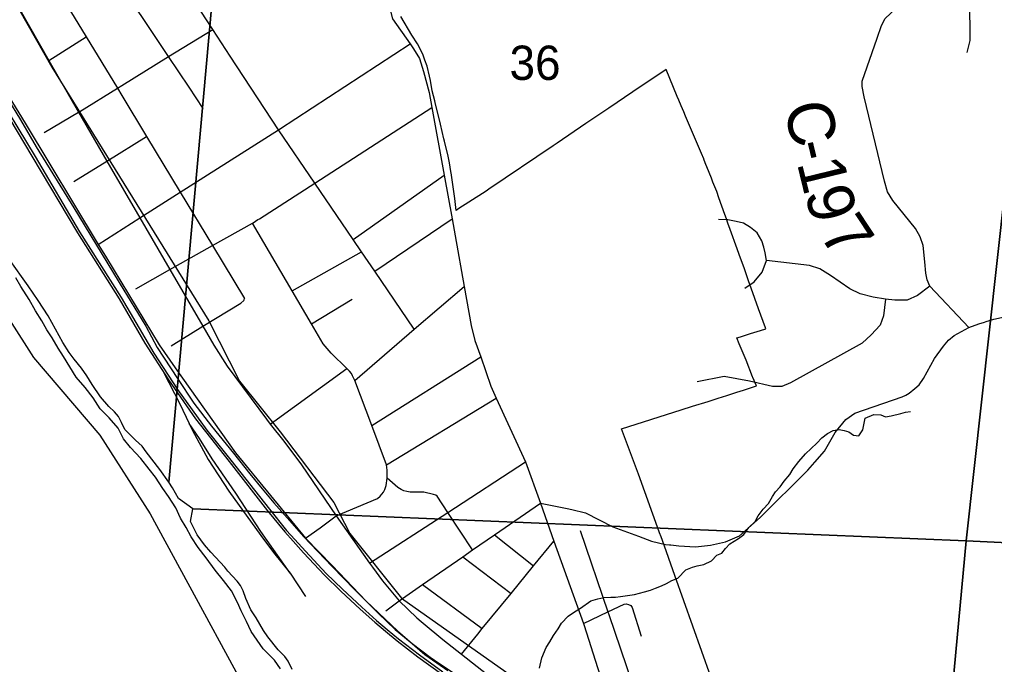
# Model space of a CAD drawing. Extents: x 0 to 34, y 0 to 22.
# Drawn here: x 3.46 to 4.65, y 16.362 to 17.149 of the extents above; entities that cross this region are included whole.
import ezdxf

# ---------------------------------------------------------------- set-up
doc = ezdxf.new("R2010")
doc.units = 0
for name, color, linetype in [('GM_X_City_Street', 7, 'Continuous'), ('GM_X_Corporation', 7, 'Continuous'), ('GM_X_County_Road', 7, 'Continuous'), ('GM_X_County_Road_Text', 7, 'Continuous'), ('GM_X_Major_River', 7, 'Continuous'), ('GM_X_Minor_River', 7, 'Continuous'), ('GM_X_Rail_Line', 7, 'Continuous'), ('GM_X_Section_Text', 7, 'Continuous'), ('GM_X_Township_Road', 7, 'Continuous'), ('GM_X_US_Route', 7, 'Continuous')]:
    doc.layers.add(name, color=color, linetype=linetype)

msp = doc.modelspace()

# ---------------------------------------------------------------- linework, layer by layer
at = {"layer": 'GM_X_City_Street'}
for p, q in [((3.4955, 17.0991), (3.5412, 17.1277)), ((3.8669, 16.8804), (3.9778, 16.9592)), ((3.8933, 16.8418), (3.9875, 16.9057)), ((3.7926, 16.8177), (3.8772, 16.8653)), ((3.816, 16.7777), (3.8655, 16.8078)), ((3.8895, 16.6536), (4.0226, 16.7375)), ((3.7657, 16.655), (3.8592, 16.7229)), ((3.9074, 16.6055), (4.0414, 16.687)), ((4.0393, 16.5199), (4.0871, 16.4823)), ((4.1438, 16.5254), (4.1777, 16.4259)), ((4.0008, 16.4933), (4.0596, 16.4486)), ((3.9516, 16.4594), (4.0245, 16.4057)), ((3.9068, 16.4272), (3.9229, 16.4395))]:
    msp.add_line(p, q, dxfattribs=at)
for points in [[(3.9415, 16.771), (3.8933, 16.8418), (3.8772, 16.8653), (3.8669, 16.8804), (3.8199, 16.9493), (3.7756, 17.0143), (3.7168, 17.1044), (3.6955, 17.1369), (3.6162, 17.2585), (3.5751, 17.3226), (3.5106, 17.423), (3.4787, 17.4728), (3.4776, 17.474), (3.4757, 17.4747)], [(3.684, 17.0404), (3.6667, 17.0663), (3.6417, 17.1037), (3.6148, 17.1441), (3.5998, 17.1666), (3.5617, 17.2245), (3.5205, 17.2872), (3.4947, 17.3265)], [(3.4432, 17.285), (3.4453, 17.2847), (3.4469, 17.2834), (3.466, 17.2519), (3.5042, 17.1888), (3.5412, 17.1277), (3.5791, 17.0651), (3.5845, 17.0563), (3.6148, 17.0061), (3.6559, 16.9382), (3.6953, 16.8731), (3.7344, 16.8086)], [(3.4899, 17.0112), (3.5317, 17.0358), (3.5334, 17.0368), (3.5791, 17.0651), (3.5846, 17.0685), (3.6417, 17.1037), (3.6955, 17.1369)], [(3.5558, 16.8746), (3.6066, 16.9069), (3.6559, 16.9382), (3.7756, 17.0143), (3.7771, 17.0152), (3.9363, 17.1193)], [(3.7524, 16.9058), (3.8199, 16.9493), (3.963, 17.0415)], [(3.5259, 16.9514), (3.5663, 16.9763), (3.6148, 17.0061)], [(3.6016, 16.8204), (3.6432, 16.8438), (3.6953, 16.8731), (3.7442, 16.9006), (3.7448, 16.9009), (3.7507, 16.9048), (3.7524, 16.9058)], [(3.8088, 16.5159), (3.8264, 16.5287), (3.846, 16.5432), (3.8964, 16.5646), (3.9, 16.5674), (3.9038, 16.5721), (3.9054, 16.5753), (3.9063, 16.5778), (3.9071, 16.5804), (3.9083, 16.5894), (3.9084, 16.5989), (3.9074, 16.6055), (3.8895, 16.6536), (3.8687, 16.7084), (3.8661, 16.7142), (3.8647, 16.7171), (3.8624, 16.7199), (3.8592, 16.7229), (3.8399, 16.7417), (3.8304, 16.7531), (3.816, 16.7777), (3.7926, 16.8177), (3.7442, 16.9006)], [(3.8687, 16.7084), (3.9415, 16.771), (4.0024, 16.8233)], [(3.6447, 16.7507), (3.6835, 16.7746), (3.7298, 16.803), (3.7333, 16.8059), (3.734, 16.807), (3.7344, 16.8086)], [(3.887, 16.4854), (3.9823, 16.5474), (4.0771, 16.6092)], [(4.0127, 16.5016), (3.9823, 16.5474), (3.9692, 16.5671), (3.9676, 16.5684), (3.9649, 16.5695), (3.9533, 16.572), (3.9363, 16.5723), (3.9325, 16.5728), (3.9288, 16.5739), (3.9254, 16.5755), (3.9213, 16.5779), (3.9083, 16.5894)], [(3.9989, 16.3745), (4.0189, 16.3988), (4.0245, 16.4057), (4.0596, 16.4486), (4.0871, 16.4823), (4.1119, 16.5125)], [(4.1478, 16.4118), (4.1777, 16.4259), (4.1976, 16.4353), (4.2002, 16.4357), (4.2029, 16.4352), (4.2058, 16.4337), (4.2075, 16.4315), (4.2184, 16.3962)], [(4.1777, 16.4259), (4.1787, 16.4228), (4.2072, 16.3389)]]:
    msp.add_lwpolyline(points, dxfattribs=at)
at = {"layer": 'GM_X_Corporation'}
for points in [[(3.7435, 17.7155), (3.6418, 16.5845), (3.6308, 16.5999), (3.6143, 16.6215), (3.6092, 16.6281), (3.6014, 16.6355), (3.5947, 16.6421), (3.5881, 16.6487), (3.5841, 16.6571), (3.5805, 16.6647), (3.5757, 16.6702), (3.5687, 16.6768), (3.5587, 16.6884), (3.5485, 16.7034), (3.5419, 16.7142), (3.5353, 16.7234), (3.5265, 16.7343), (3.5203, 16.7427), (3.5126, 16.7547), (3.4948, 16.7873), (3.4824, 16.8062), (3.4703, 16.8239), (3.4623, 16.8355), (3.4483, 16.8547)], [(4.3035, 16.3468), (4.2595, 16.4705), (4.2443, 16.5132), (4.2426, 16.5178), (4.2409, 16.5225), (4.2403, 16.5239), (4.215, 16.5941), (4.2103, 16.6071), (4.1945, 16.6493), (4.267, 16.6726), (4.2808, 16.677), (4.3, 16.683), (4.3122, 16.6869), (4.3229, 16.6903), (4.3351, 16.6942), (4.3392, 16.6955), (4.3432, 16.6968), (4.359, 16.7018), (4.359, 16.702), (4.3547, 16.7123), (4.3544, 16.7131), (4.3463, 16.7331), (4.3381, 16.753), (4.335, 16.7605), (4.3396, 16.7619), (4.3517, 16.7656), (4.3639, 16.7693), (4.3705, 16.7713), (4.37, 16.7727), (4.3616, 16.7961), (4.3527, 16.8211), (4.351, 16.8256), (4.3494, 16.8302), (4.3443, 16.8446), (4.338, 16.8622), (4.3355, 16.8692), (4.327, 16.8929), (4.3242, 16.9006), (4.3224, 16.9058), (4.3205, 16.911), (4.3133, 16.9313), (4.3105, 16.9391), (4.3059, 16.9507), (4.3041, 16.9553), (4.3012, 16.9623), (4.2966, 16.974), (4.2949, 16.9784), (4.2947, 16.9788), (4.2919, 16.9854), (4.2871, 16.9969), (4.2822, 17.0083), (4.2774, 17.0197), (4.2725, 17.0312), (4.2704, 17.0363), (4.2673, 17.0437), (4.2643, 17.0507), (4.2624, 17.0551), (4.2487, 17.088), (4.2081, 17.0606), (4.1787, 17.0408), (4.151, 17.022), (4.1157, 16.9981), (4.111, 16.9949), (4.0325, 16.9419), (4.029, 16.9396), (4.0246, 16.9367), (3.996, 16.9182), (3.9926, 16.9158), (3.9908, 16.9306), (3.9905, 16.9336), (3.9885, 16.9477), (3.9868, 16.9592), (3.9868, 16.9593), (3.9862, 16.9636), (3.9846, 16.9743), (3.9829, 16.9822), (3.9784, 17.0004), (3.9777, 17.0036), (3.9733, 17.0214), (3.9669, 17.0477), (3.9664, 17.0496), (3.9632, 17.062), (3.9612, 17.0748), (3.9601, 17.0798), (3.957, 17.0921), (3.9545, 17.0996), (3.9522, 17.1054), (3.95, 17.1107), (3.9452, 17.1193), (3.9385, 17.1301), (3.925, 17.1527)], [(3.3535, 16.9293), (3.4766, 16.7367), (3.5579, 16.6419), (3.619, 16.5459), (3.7774, 16.2543), (3.8686, 16.1561), (3.9643, 16.0792), (4.2564, 15.9374), (4.3533, 15.9108), (4.4487, 15.8964), (4.6416, 15.8532), (4.7366, 15.8475), (5.0291, 15.8581), (5.1241, 15.8236), (5.4143, 15.7071), (5.7095, 15.5281), (5.8045, 15.4515), (6.1414, 15.0678), (6.2843, 14.8736), (6.3804, 14.7819), (6.459, 14.6859)], [(3.3535, 16.9293), (3.4766, 16.7367), (3.5579, 16.6419), (3.619, 16.5459), (3.7774, 16.2543), (3.8686, 16.1561), (3.9643, 16.0792), (4.2564, 15.9374), (4.3533, 15.9108), (4.4487, 15.8964), (4.6416, 15.8532), (4.7366, 15.8475), (5.0291, 15.8581), (5.1241, 15.8236), (5.4143, 15.7071), (5.7095, 15.5281), (5.8045, 15.4515), (6.1354, 15.0636), (6.1959, 14.9814), (6.2842, 14.8736), (6.3804, 14.7819), (6.459, 14.6859)], [(3.3535, 16.9293), (3.4766, 16.7367), (3.5579, 16.6419), (3.619, 16.5459), (3.7774, 16.2543), (3.8686, 16.1561), (3.9643, 16.0792), (4.2564, 15.9374), (4.3533, 15.9108), (4.4487, 15.8964), (4.6416, 15.8532), (4.7366, 15.8475), (5.0291, 15.8581), (5.1241, 15.8236), (5.4143, 15.7071), (5.7095, 15.5281), (5.8045, 15.4515), (6.1414, 15.0678), (6.2843, 14.8736), (6.3804, 14.7819), (6.459, 14.6859)], [(3.7923, 16.3558), (3.7877, 16.3657), (3.7836, 16.3715), (3.7755, 16.3797), (3.7626, 16.3955), (3.7575, 16.4032), (3.7484, 16.4186), (3.7418, 16.4286), (3.7357, 16.4424), (3.7325, 16.4516), (3.7293, 16.4581), (3.7253, 16.4635), (3.7138, 16.4759), (3.7101, 16.4805), (3.6932, 16.4991), (3.6854, 16.508), (3.6766, 16.52), (3.6683, 16.5365), (3.671, 16.5519), (4.6148, 16.5127), (4.5615, 15.9382)], [(4.6515, 15.9489), (4.6363, 15.9455), (4.6211, 15.9424), (4.6089, 15.9389), (4.5952, 15.937), (4.5846, 15.9369), (4.5725, 15.9375), (4.5615, 15.9382), (4.6148, 16.5127), (5.7092, 16.4608)]]:
    msp.add_lwpolyline(points, dxfattribs=at)
for points in [[(4.7377, 17.6243), (4.6148, 16.5127), (3.671, 16.5519), (3.6538, 16.5645), (3.6462, 16.5775), (3.6418, 16.5845), (3.7435, 17.7155)], [(5.7989, 17.4561), (5.7092, 16.4608), (4.6148, 16.5127), (4.7377, 17.6243)]]:
    msp.add_lwpolyline(points, close=True, dxfattribs=at)
at = {"layer": 'GM_X_County_Road'}
for points in [[(3.8656, 17.3796), (3.8661, 17.3752), (3.9094, 17.1706), (3.9115, 17.1626), (3.915, 17.15), (3.9363, 17.1193), (3.9407, 17.1131), (3.9477, 17.1015), (3.9526, 17.0855), (3.9596, 17.0599), (3.963, 17.0415), (3.9778, 16.9592), (3.9875, 16.9057), (3.9912, 16.8851)], [(4.6183, 16.773), (4.5705, 16.8235), (4.5673, 16.8314), (4.5659, 16.8396), (4.5647, 16.8532), (4.5625, 16.8732), (4.5587, 16.8838), (4.5533, 16.894), (4.5253, 16.9283), (4.519, 16.9389), (4.5152, 16.9519), (4.4903, 17.0548), (4.4879, 17.0674), (4.4881, 17.0736), (4.5065, 17.1263), (4.5116, 17.1417), (4.5162, 17.1504), (4.5427, 17.1753), (4.5473, 17.1852), (4.549, 17.1954), (4.5427, 17.2176), (4.5372, 17.2388), (4.5294, 17.2707)], [(3.4403, 17.1954), (3.4599, 17.1612), (3.4955, 17.0991), (3.5317, 17.0358), (3.5663, 16.9763), (3.6066, 16.9069), (3.6432, 16.8438), (3.6835, 16.7746), (3.6969, 16.7516), (3.713, 16.7258), (3.7609, 16.6611), (3.7657, 16.655), (3.7823, 16.6344), (3.804, 16.6055), (3.846, 16.5432), (3.887, 16.4854), (3.8904, 16.4808), (3.9025, 16.4638), (3.9229, 16.4395), (3.9444, 16.4189), (3.95, 16.4142), (3.9523, 16.4123)], [(3.9912, 16.8851), (4.0024, 16.8233), (4.0107, 16.7755), (4.0152, 16.7572), (4.0226, 16.7375), (4.0348, 16.7014), (4.0414, 16.687), (4.0771, 16.6092), (4.0954, 16.5586), (4.1119, 16.5125), (4.1478, 16.4118), (4.1486, 16.4096), (4.1761, 16.3236)], [(4.6374, 16.7798), (4.6393, 16.7804), (4.6488, 16.7833), (4.6689, 16.7878), (4.6868, 16.7916), (4.698, 16.7956), (4.7108, 16.8004), (4.7329, 16.8106), (4.7521, 16.8171), (4.7744, 16.8212), (4.8004, 16.8239), (4.8298, 16.8239), (4.8756, 16.8228), (4.9193, 16.8226), (4.9416, 16.8253), (4.9543, 16.8284), (4.9651, 16.834), (4.9791, 16.8397), (4.9919, 16.8418), (5.0061, 16.8441), (5.0259, 16.8461), (5.1922, 16.8534)], [(4.2547, 16.5077), (4.2645, 16.5068), (4.2846, 16.5056), (4.3029, 16.5075), (4.3211, 16.5117), (4.3384, 16.5189), (4.3635, 16.5411), (4.4217, 16.599), (4.4302, 16.6087), (4.4421, 16.6223), (4.4549, 16.6448), (4.4683, 16.661), (4.479, 16.6686), (4.5369, 16.6884), (4.5412, 16.6905), (4.5453, 16.6929), (4.5525, 16.6987), (4.5575, 16.703), (4.5631, 16.7108), (4.5764, 16.7352), (4.5872, 16.7502), (4.5935, 16.7576), (4.6003, 16.7633), (4.6183, 16.773), (4.6306, 16.7776), (4.6374, 16.7798)], [(3.9229, 16.4395), (3.9516, 16.4594), (4.0008, 16.4933), (4.0127, 16.5016), (4.0393, 16.5199), (4.0954, 16.5586)], [(4.0954, 16.5586), (4.1282, 16.5522), (4.1338, 16.5509)], [(4.1338, 16.5509), (4.1505, 16.5468), (4.1839, 16.5298), (4.2151, 16.5185), (4.2309, 16.5125), (4.2479, 16.5083), (4.2528, 16.5079), (4.2547, 16.5077)], [(3.9523, 16.4123), (3.9761, 16.3925), (3.9989, 16.3745), (4.0927, 16.3007), (4.0935, 16.2993), (4.0936, 16.2976), (4.0934, 16.2958), (4.093, 16.2942), (4.091, 16.2887)]]:
    msp.add_lwpolyline(points, dxfattribs=at)
at = {"layer": 'GM_X_Major_River'}
for points in [[(3.6416, 16.5667), (3.6345, 16.5767), (3.6256, 16.5905), (3.6178, 16.6001), (3.6078, 16.6132), (3.5951, 16.6267), (3.5866, 16.6374), (3.5799, 16.6504), (3.5691, 16.6628), (3.5583, 16.6739), (3.5494, 16.6874), (3.5397, 16.7), (3.5289, 16.7127), (3.5212, 16.725), (3.5134, 16.7377), (3.5067, 16.748), (3.4994, 16.7606), (3.4931, 16.7702), (3.4868, 16.7813), (3.479, 16.7936), (3.4713, 16.8074), (3.4613, 16.8231), (3.455, 16.8338)], [(3.7782, 16.3565), (3.7708, 16.3673), (3.757, 16.3808), (3.7496, 16.3915), (3.7425, 16.4019), (3.7367, 16.4141), (3.73, 16.4275), (3.7257, 16.4375), (3.7183, 16.4516), (3.7086, 16.4643), (3.6986, 16.477), (3.6874, 16.492), (3.6778, 16.5047), (3.6693, 16.5177), (3.663, 16.5292), (3.6563, 16.5403), (3.6505, 16.5529), (3.6416, 16.5667)]]:
    msp.add_lwpolyline(points, dxfattribs=at)
at = {"layer": 'GM_X_Minor_River'}
for points in [[(4.5411, 16.6698), (4.5472, 16.6708)], [(4.0944, 16.3573), (4.0973, 16.3698), (4.1025, 16.3826), (4.1068, 16.3894), (4.1115, 16.3973), (4.117, 16.4052), (4.121, 16.4123), (4.1291, 16.4209), (4.1357, 16.4254), (4.1442, 16.4306), (4.157, 16.4395), (4.1654, 16.442), (4.1727, 16.4434), (4.1815, 16.444), (4.1872, 16.4439), (4.193, 16.4449), (4.2102, 16.4473), (4.2225, 16.4505), (4.2298, 16.4526), (4.2359, 16.4548), (4.2432, 16.4577), (4.2494, 16.4606), (4.2559, 16.4643), (4.2629, 16.4672), (4.273, 16.4773), (4.281, 16.4806), (4.2868, 16.4824), (4.2949, 16.4838), (4.3041, 16.4882), (4.3107, 16.4953), (4.3169, 16.4978), (4.3212, 16.5034), (4.3266, 16.509), (4.3371, 16.5157), (4.3436, 16.5205), (4.3499, 16.5292), (4.3573, 16.5362), (4.3612, 16.5434), (4.3671, 16.5513), (4.3737, 16.5584), (4.3785, 16.5667), (4.3824, 16.5727), (4.3878, 16.5787), (4.3929, 16.5854), (4.3996, 16.5937), (4.4039, 16.6008), (4.4109, 16.6094), (4.4187, 16.6188), (4.4327, 16.6318), (4.439, 16.6386), (4.4456, 16.6438), (4.4525, 16.6475), (4.4598, 16.6488), (4.4659, 16.6476), (4.4719, 16.6456), (4.4776, 16.6417), (4.4841, 16.6408), (4.4888, 16.6483), (4.4917, 16.6623), (4.5021, 16.6671), (4.5109, 16.6666), (4.5166, 16.6642), (4.5235, 16.6652), (4.5353, 16.668), (4.5411, 16.6698)]]:
    msp.add_lwpolyline(points, dxfattribs=at)
at = {"layer": 'GM_X_Rail_Line'}
msp.add_line((3.7901, 16.4732), (3.8088, 16.4449), dxfattribs=at)
for points in [[(3.4206, 17.2288), (3.4993, 17.0909), (3.6906, 16.7811), (3.7282, 16.7075), (3.7776, 16.6456), (3.8431, 16.5595), (3.8629, 16.5219), (3.926, 16.4427), (4.06, 16.3478), (4.1978, 16.275), (4.2934, 16.2188), (4.3976, 16.1705), (4.4935, 16.127), (4.6314, 16.1011), (4.6907, 16.0865)], [(3.4287, 17.0786), (3.4607, 17.0265), (3.4802, 16.9936), (3.5258, 16.9193), (3.5869, 16.8185), (3.6139, 16.7746), (3.6277, 16.7487), (3.6526, 16.711), (3.6726, 16.6809), (3.6938, 16.6526), (3.7208, 16.6199), (3.7407, 16.5945), (3.7557, 16.5764), (3.7702, 16.5593), (3.7862, 16.5407), (3.8061, 16.5181), (3.8414, 16.4815), (3.8688, 16.453), (3.8974, 16.4243), (3.9182, 16.4046), (3.939, 16.3874), (3.9608, 16.3707), (3.9725, 16.3628), (4.0028, 16.3425)], [(3.4206, 17.0725), (3.4747, 16.9821), (3.5303, 16.8888), (3.5813, 16.8082), (3.6125, 16.754), (3.6417, 16.7092), (3.6744, 16.6618), (3.7154, 16.6094), (3.7624, 16.5495), (3.7835, 16.5237), (3.7935, 16.5123), (3.8064, 16.4983), (3.8318, 16.4707), (3.8517, 16.4515), (3.8753, 16.4295), (3.8933, 16.4135), (3.9064, 16.4023), (3.9204, 16.3907), (3.9459, 16.3712), (3.9745, 16.3505)], [(3.4244, 17.0713), (3.4787, 16.9817), (3.533, 16.89), (3.5838, 16.8097), (3.6238, 16.7416), (3.6524, 16.6975), (3.6883, 16.6478), (3.7177, 16.6112), (3.7646, 16.5513), (3.7857, 16.5255), (3.7956, 16.5142), (3.8086, 16.5002), (3.8339, 16.4728), (3.8537, 16.4536), (3.8773, 16.4317), (3.8952, 16.4157), (3.9083, 16.4045), (3.9222, 16.393), (3.9477, 16.3735), (3.9761, 16.3529)], [(3.6355, 16.7187), (3.6554, 16.6799), (3.6668, 16.6559)], [(3.7901, 16.4732), (3.7543, 16.5242), (3.7235, 16.5708), (3.6946, 16.613), (3.6794, 16.6375), (3.6668, 16.6559)], [(3.6668, 16.6559), (3.6704, 16.6482), (3.69, 16.6121), (3.7152, 16.5735), (3.7542, 16.5191), (3.7696, 16.4987), (3.7901, 16.4732)]]:
    msp.add_lwpolyline(points, dxfattribs=at)
at = {"layer": 'GM_X_Township_Road'}
for points in [[(4.616, 17.1089), (4.6197, 17.1233), (4.6194, 17.1739), (4.6174, 17.1813), (4.6142, 17.187), (4.6084, 17.1944), (4.602, 17.198), (4.5946, 17.2008), (4.5878, 17.2021), (4.5804, 17.2014), (4.5646, 17.1987), (4.549, 17.1954)], [(4.345, 16.821), (4.3562, 16.8287), (4.3661, 16.8407), (4.3713, 16.8551), (4.3698, 16.8642), (4.368, 16.8712), (4.3657, 16.8788), (4.36, 16.8885), (4.3517, 16.8953), (4.3432, 16.9005), (4.3344, 16.9025), (4.3241, 16.9044), (4.3127, 16.9048)], [(4.5705, 16.8235), (4.5556, 16.8123), (4.5431, 16.8065), (4.528, 16.8063), (4.5165, 16.8079), (4.5016, 16.8103), (4.4855, 16.8144), (4.4731, 16.8203), (4.4496, 16.8365), (4.4363, 16.8447), (4.4237, 16.8487), (4.3713, 16.8551)], [(4.5165, 16.8079), (4.5142, 16.7875), (4.5101, 16.7759), (4.4991, 16.7642), (4.4882, 16.7539), (4.4004, 16.7054), (4.3899, 16.7011), (4.3785, 16.7011), (4.3504, 16.7077)], [(4.3504, 16.7077), (4.3196, 16.7134), (4.2866, 16.707)]]:
    msp.add_lwpolyline(points, dxfattribs=at)
at = {"layer": 'GM_X_US_Route'}
msp.add_lwpolyline([(3.3492, 17.2141), (3.4666, 17.0225), (3.5558, 16.8746), (3.5646, 16.8601), (3.6301, 16.7521), (3.6497, 16.7238), (3.7234, 16.6203), (3.8088, 16.5159), (3.8414, 16.4825), (3.8826, 16.4393), (3.9211, 16.403), (3.9543, 16.3742), (3.9822, 16.3543)], dxfattribs=at)

# ---------------------------------------------------------------- texts
at = {"layer": 'GM_X_County_Road_Text'}
for s, rotation, p in [('C', 282.8865, (4.3921, 17.0431)), ('-', 283.6044, (4.4027, 16.9968)), ('1', 283.7063, (4.4082, 16.9741)), ('9', 286.1447, (4.4172, 16.9375)), ('7', 303.3685, (4.4347, 16.887))]:
    msp.add_text(s, height=0.0568, rotation=rotation, dxfattribs=at).set_placement(p)
at = {"layer": 'GM_X_Section_Text'}
msp.add_text('36', height=0.04186, rotation=0, dxfattribs=at).set_placement((4.0577, 17.0753))

doc.saveas('drawing.dxf')
